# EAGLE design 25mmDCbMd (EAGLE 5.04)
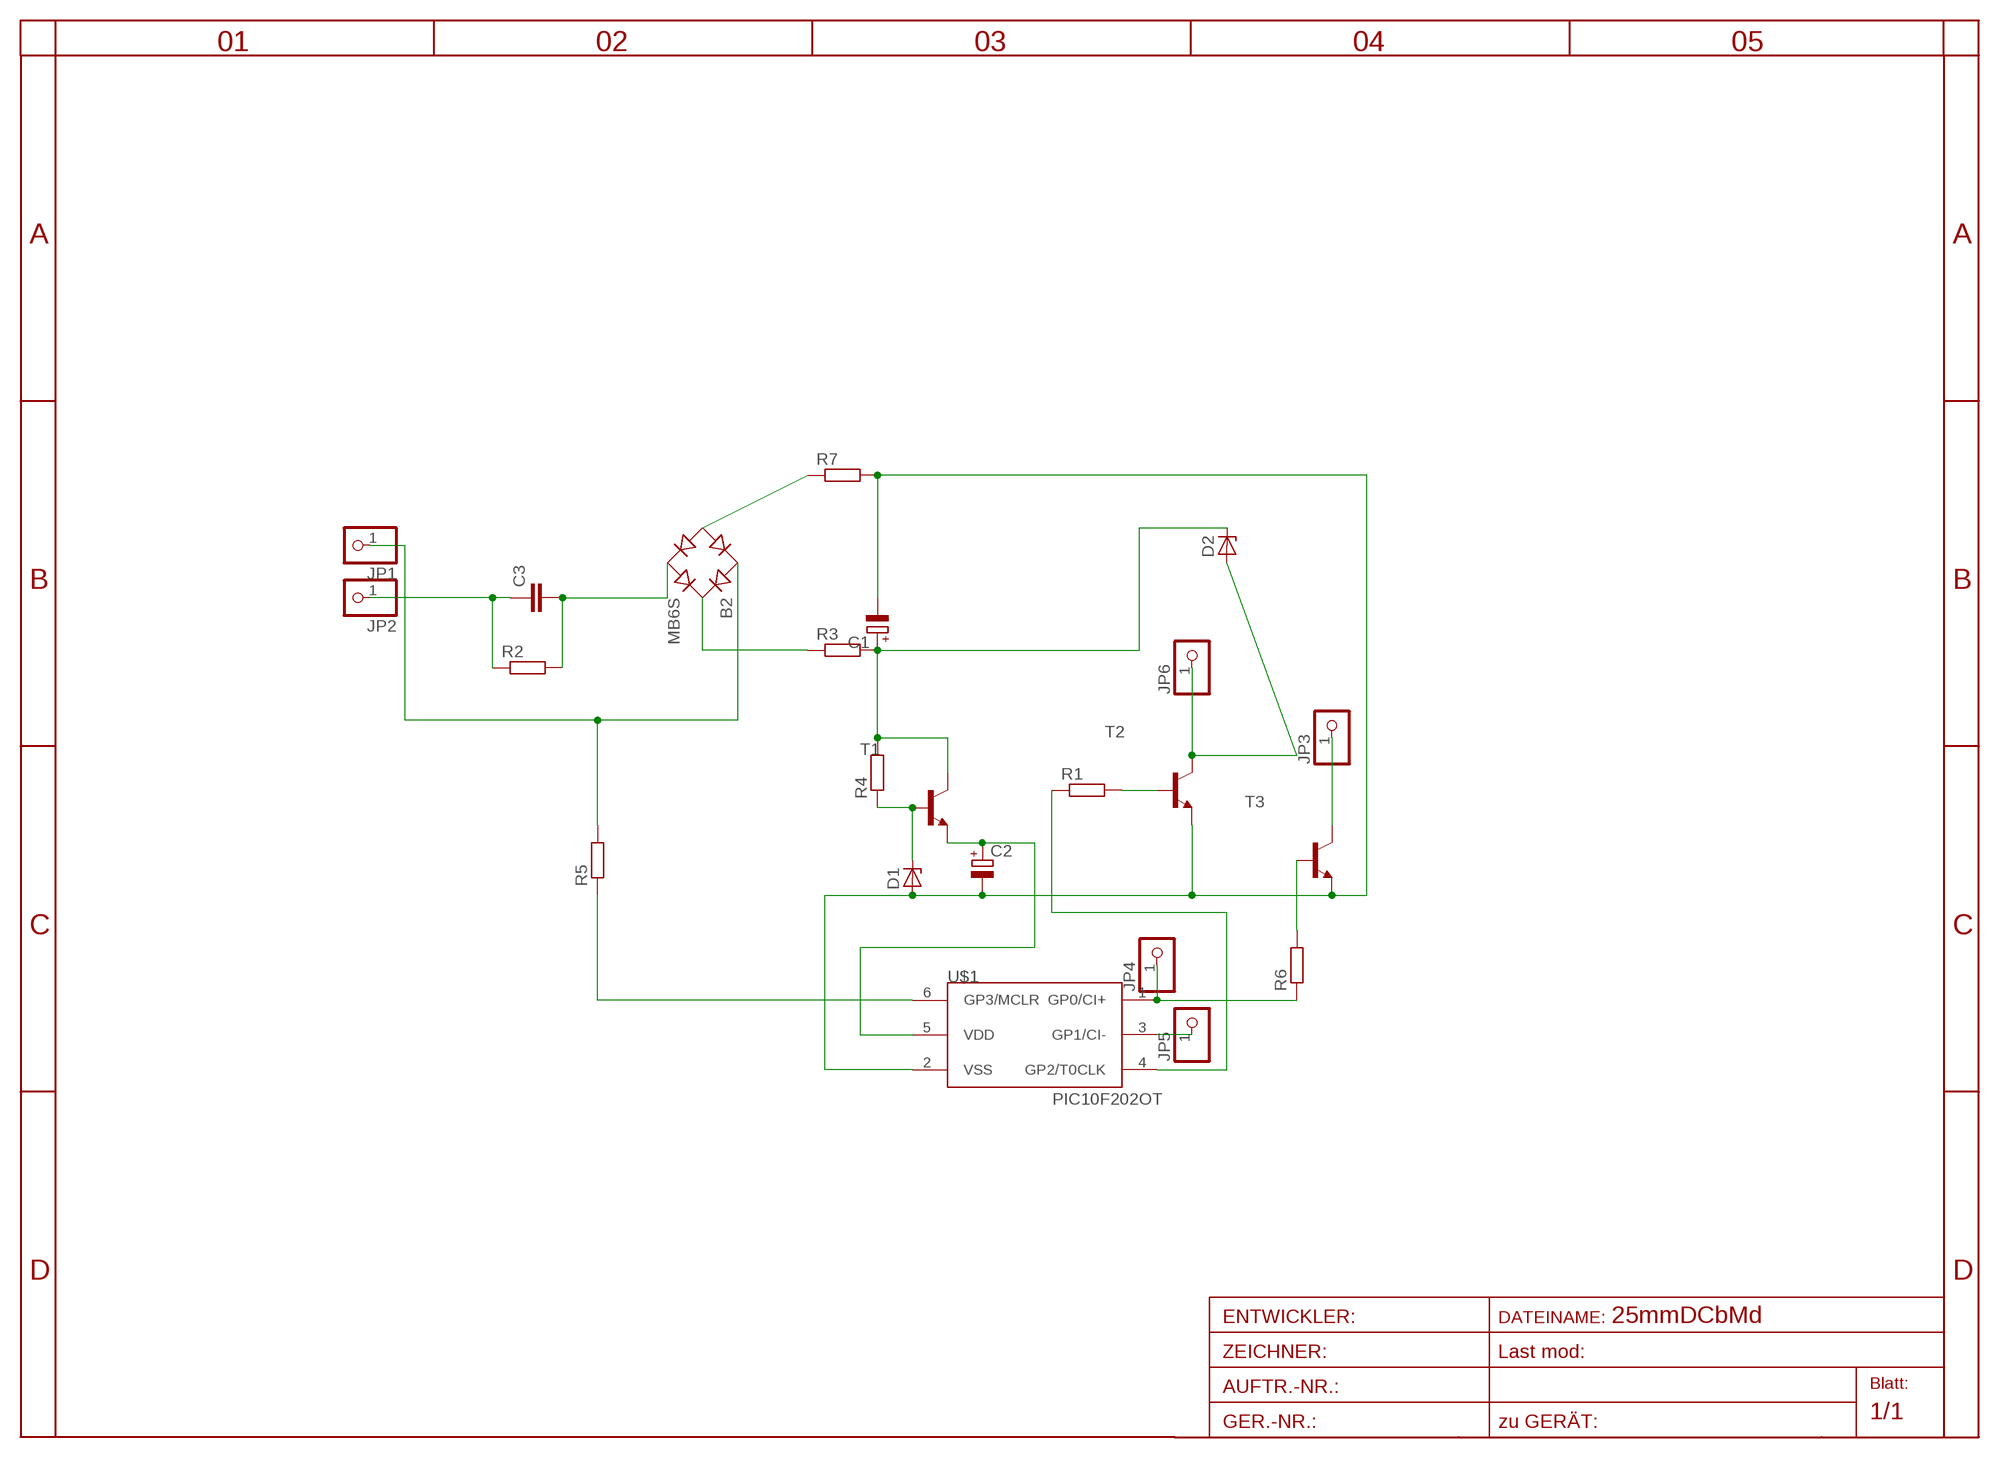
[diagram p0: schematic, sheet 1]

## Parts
B2  MB6S  [SOIC-4]
C1  CPOL-EUE5-8.5  [E5-8,5]
C2  CPOL-EUE2.5-6  [E2,5-6]
C3  C-EU150-054X183  [C150-054X183]
D1  ZENER-DIODESOD80C  [SOD80C]
D2  ZENER-DIODESOD80C  [SOD80C]
JP1  PINHD-1X1  [1X01]
JP2  PINHD-1X1  [1X01]
JP3  PINHD-1X1  [1X01]
JP4  PINHD-1X1  [1X01]
JP5  PINHD-1X1  [1X01]
JP6  PINHD-1X1  [1X01]
R1  R-EU_R0805  [R0805]
R2  R-EU_R1206  [R1206]
R3  R-EU_R1206  [R1206]
R4  R-EU_R0805  [R0805]
R5  R-EU_R0805  [R0805]
R6  R-EU_R0805  [R0805]
R7  R-EU_R1206  [R1206]
T1  BC846BLT1-NPN-SOT23-BEC  [SOT23-BEC]
T2  BC846BLT1-NPN-SOT23-BEC  [SOT23-BEC]
T3  BC846BLT1-NPN-SOT23-BEC  [SOT23-BEC]
U$1  PIC10F202OT  [SOT23-6]

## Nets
AC: B2.~1(AC1) JP1.1 R5.2
AC+: C3.1 JP2.1 R2.1
LOAD/COIL: D2.A JP6.1 T2.C
MINUS: C1.- C2.- D1.A R7.2 T2.E T3.E U$1.2(VSS)
N$1: B2.~2(AC2) C3.2 R2.2
N$2: B2.+ R3.1
N$3: R5.1 U$1.6(GP3/MCLR)
N$4: R6.2 T3.B
N$6: D1.C R4.1 T1.B
N$8: R1.2 T2.B
N$9: JP3.1 T3.C
N$10: B2.- R7.1
N$11: R1.1 U$1.4(GP2/T0CLK)
N$12: JP4.1 R6.1 U$1.1(GP0/CI+)
N$13: JP5.1 U$1.3(GP1/CI-)
PLUS: C1.+ D2.C R3.2 R4.2 T1.C
VDD: C2.+ T1.E U$1.5(VDD)

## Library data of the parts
B2 = rectifier:MB*S: Bridge Rectifier Source: http://www.fairchildsemi.com/ds/MB/MB6S.pdf
C1 = rcl-2:CPOL-EU: POLARIZED CAPACITOR, European symbol
C2 = rcl:CPOL-EU: POLARIZED CAPACITOR, European symbol
C3 = rcl:C-EU: CAPACITOR, European symbol
D1 D2 = diode-1:ZENER-DIODE: Z-Diode
JP1-JP6 = pinhead:PINHD-1X1: PIN HEADER
R1-R7 = rcl:R-EU_: RESISTOR, European symbol
T1-T3 = transistor:*-NPN-: NPN Transistror BF959 corrected 2008.03.06
U$1 = microchip-5:PIC10F2*: uPC nW 0,25/0,5k Program Flash memory Comparator

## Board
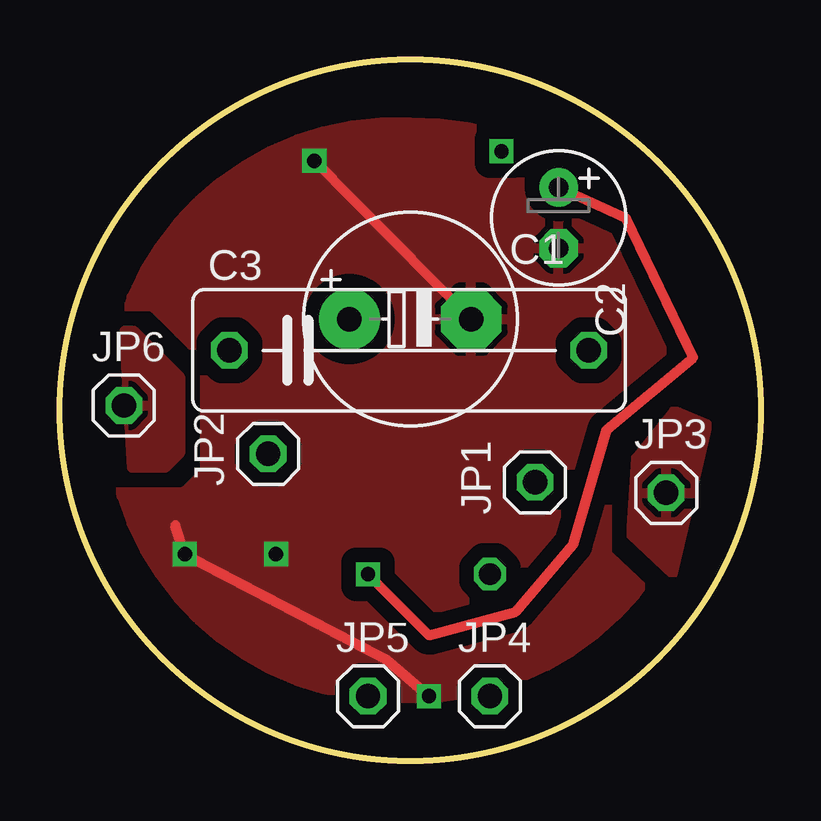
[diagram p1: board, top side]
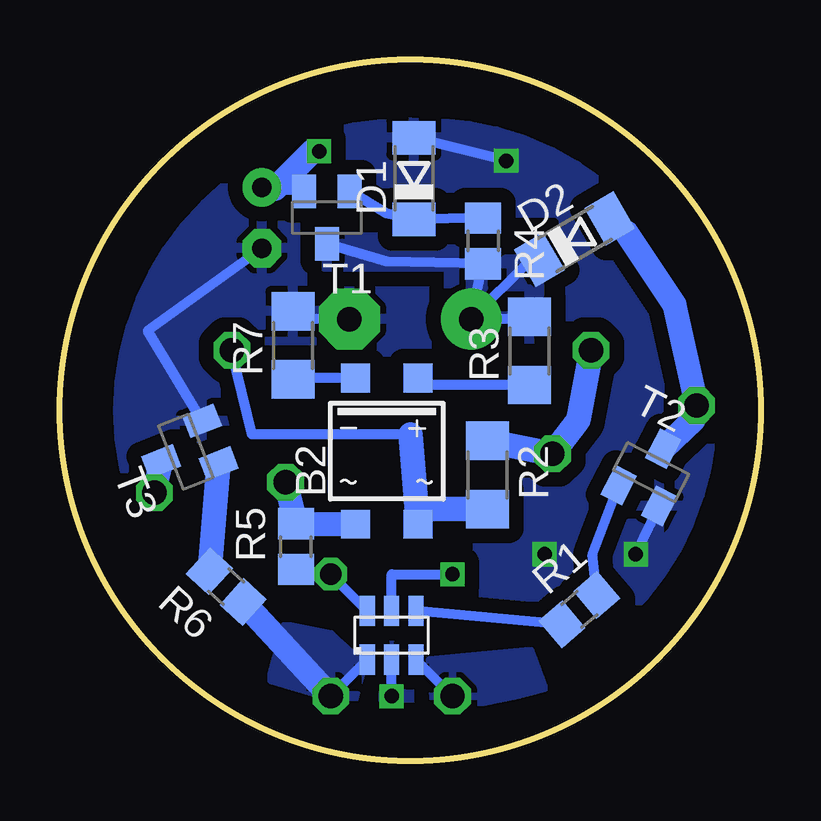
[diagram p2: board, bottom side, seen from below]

Size 29.21 x 29.21 mm. Coordinates in mm from the lower left corner, seen from the top.
Outline: circle at 14.61,14.61 radius 14.61
Copper layers (1*16): Top 0.035mm / dielectric 1.5mm / Bottom 0.035mm
Design rules "default *": minimum track width 10mil, minimum drill 24mil, track to track 8mil, track to pad 8mil, pad to pad 8mil, via to via 8mil, smd to smd 8mil, copper to edge 20mil, drill to drill 8mil, minimum pad ring 10mil, minimum via ring 8mil, stop-mask expansion 4mil, vias tented up to drill 0mil, thermal gap 10mil

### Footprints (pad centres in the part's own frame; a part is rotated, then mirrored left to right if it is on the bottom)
SOIC-4 = smd 1.2 x 1.2: + 1.3,3.05; - -1.3,3.05; ~1 -1.3,-3.05; ~2 1.3,-3.05
E5-8,5 = drill 1.016 pad 2.54 round: + -2.54,0 | drill 1.016 pad 2.54 octagon: - 2.54,0
E2,5-6 = drill 0.813 pad 1.6 round: + -1.27,0 | drill 0.813 pad 1.6 octagon: - 1.27,0
C150-054X183 = drill 1.016 octagon: 1 -7.493,0; 2 7.493,0
SOD80C = smd 1.4 x 1.8: A 1.7,0; C -1.7,0
1X01 = drill 1.016 octagon: 1 0,0
R0805 = smd 1.3 x 1.5: 1 -0.95,0; 2 0.95,0
R1206 = smd 1.6 x 1.803: 1 -1.422,0; 2 1.422,0
SOT23-BEC = smd 1 x 1.4: B -0.95,-1.1; C 0,1.1; E 0.95,-1.1
SOT23-6 = smd 0.635 x 1.27: 1 -1.016,-1.016; 2 0,-1.016; 3 1.016,-1.016; 4 1.016,1.016; 5 0,1.016; 6 -1.016,1.016

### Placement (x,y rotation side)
B2  15.59,12.91 0 bottom
C1  14.61,18.41 0 top
C2  20.79,22.63 270 top
C3  14.55,17.11 0 top
D1  14.46,24.27 90 bottom
D2  7.76,21.74 30.4 bottom
JP1  19.8,11.61 90 top
JP2  8.68,12.79 90 top
JP3  25.28,11.17 0 top
JP4  17.93,2.69 0 top
JP5  12.85,2.69 0 top
JP6  2.67,14.8 0 top
R1  7.55,6.29 40.3 bottom
R2  11.38,11.91 270 bottom
R3  9.64,17.08 90 bottom
R4  11.57,21.66 270 bottom
R5  19.38,8.93 90 bottom
R6  22.28,7.26 137.6 bottom
R7  19.5,17.32 90 bottom
T1  18.08,22.64 180 bottom
T2  4.57,12.03 332.7 bottom
T3  23.96,12.88 111.3 bottom
U$1  15.39,5.23 0 bottom

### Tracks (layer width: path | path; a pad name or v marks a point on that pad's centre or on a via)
AC
  Bottom 1.016: JP1.1 R5.2 B2.~1
AC+
  Bottom 1.016: R2.1 JP2.1 7.61,14.21 C3.1
LOAD/COIL
  Bottom 0.406: 5.61,22 D2.A | JP6.1 2.81,14.21
  Bottom 1.016: 5.61,22 3.61,19 JP6.1 | 2.81,14.21 T2.C
  pour Top (isolate 0.61): 2.69,17.93 3.09,17.93 5.01,16 5.01,12.8 4.41,12.21 3.01,12.21
MINUS  (via drill 0.6)
  Top 0.406: v15.39,2.69 13.59,4.23 v5.21,8.61 4.81,9.8 | C1.- v10.61,25
  Bottom 0.406: R7.2 19.16,18.41 C1.- | T3.E 25.55,17.93 C2.- | v15.39,2.69 U$1.2 | v5.21,8.61 T2.E | v10.61,25 D1.A
  other vias: 9.01,8.61
  pour Top (isolate 0.61, rank 3): 14.61,26.61 arc185 14.61,2.61 arc182
  pour Bottom (isolate 0.61, rank 3): 14.61,26.61 arc185 14.61,2.61 arc182
N$1
  Bottom 0.406: C3.2 21.21,13.61 14.61,13.61 | B2.~2 13.66,10.48
  Bottom 1.016: B2.~2 14.61,13.61 | 13.66,10.48 R2.2
N$2
  Bottom 0.406: B2.+ 13.99,15.66 R3.1
N$3
  Bottom 0.406: U$1.6 17.93,7.77 R5.1
N$4
  Bottom 1.016: R6.2 T3.B
N$6
  Bottom 0.406: R4.1 D1.C 15.61,22.8 T1.B
N$7  (via drill 0.9)
  other vias: 17.93,7.77
N$8
  Bottom 0.406: R1.2 7.01,8.61 T2.B
N$9
  Bottom 1.016: T3.C JP3.1
  pour Top (isolate 0.61): 25.55,7.77 27,14 25.61,14.61 24,12.61 23.8,9.41
N$10
  Bottom 0.406: R7.1 19.43,15.96 B2.-
N$11
  Bottom 0.406: R1.1 U$1.4
N$12
  Bottom 0.406: U$1.1 JP4.1
  Bottom 1.016: JP4.1 R6.1
  pour Bottom (isolate 0.61): 17.93,5.23 19.8,5.61 20.41,3.41 17,2.41 16.61,4.01
N$13
  Bottom 0.406: JP5.1 U$1.3
  pour Bottom (isolate 0.61): 10.3,2.69 9.01,3.01 9.61,4.61 13.8,4.21 13.61,2.01
PLUS
  Bottom 0.406: R3.2 9.68,18.41 C1.+ | C1.+ 9.6,20.87 9.61,21 D2.C | T1.C 15.61,20.8 R4.2 C1.+
  pour Bottom (isolate 0.61, rank 2): 9.21,21.8 18.21,21.8 18.21,21.41 18.21,20.61 13.01,20.61 13.01,17.61 9.21,17.61 9.21,18.41
VDD  (via drill 0.6)
  Top 0.406: C2.+ 23.61,22.61 26.41,16.8 22.8,13.8 21.41,9.01 19,6.21 15.39,5.23 v12.85,7.77
  Bottom 0.406: U$1.5 15.39,7.77 v12.85,7.77 | T1.E 20.24,23.85 C2.+
  Bottom 1.016: v18.41,25.41 18.68,25.41 20.24,23.85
